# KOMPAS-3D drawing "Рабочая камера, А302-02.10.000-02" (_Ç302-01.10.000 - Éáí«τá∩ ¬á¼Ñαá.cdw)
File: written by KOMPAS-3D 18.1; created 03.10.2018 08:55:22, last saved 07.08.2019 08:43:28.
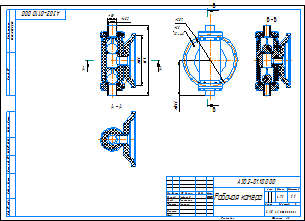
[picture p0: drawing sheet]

Sheet 1: A3, landscape

Document properties: Автор: Милов; Полное имя файла: D:\Мембранные насосы\Мембранный электропривод\А302-00.00.000 - ASTRA-302 (МЭ200)\3Д ПВХ\А302-01.10.000 - Рабочая камера.cdw; Масса: 4.93

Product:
- Part/product: Рабочая камера  | designation А302-02.10.000-02  | pos. 0
    Масса: 6.96767
    Раздел спецификации: Сборочные единицы
    Форматы листов документа: A3
  - Component [assembly]: Крышка рабочей камеры  | designation А302-02.11.000-02  | pos. 1  | Масса: 5.30764; Раздел спецификации: Сборочные единицы; Форматы листов документа: A3; source file: А302-01.11.000 - Крышка рабочей камеры.a3d
  - Component [detail]: Седло  | designation А302-01.10.001  | qty 2  | pos. 3  | Материал: Фторопласт-4  ГОСТ 10007-80 Е (density 2200 kg/m3); Масса: 0.0789763; Раздел спецификации: Детали; Форматы листов документа: A4; source file: \\192.168.87.28\Konstructor_doc\Мембранные насосы\Мембранный электропривод\А302-00.00.000 - ASTRA-302 (МЭ200)\3Д ПВХ\А302-01.10.001 - Седло.cdw, А302-01.10.001 - Седло.m3d
  - Component [assembly]: Прижим  | designation А302-01.30.000  | qty 2  | pos. 2  | Материал: Полиамид П-12Б-20  ТУ 6-05-898-73 (density 1020 kg/m3); Масса: 0.266873; Раздел спецификации: Сборочные единицы; Форматы листов документа: A3; source file: А302-01.30.000 - Прижим.a3d, А302-01.30.000 - Прижим.cdw
  - Component [detail]: Штифт 10х40  | qty 4  | pos. 86  | Масса: 0.0246804; Раздел спецификации: Детали; source file: Штифт 10х40.m3d
- Part/product: Рабочая камера  | designation А302-02.10.000-01  | pos. 0
    Масса: 10.6499
    Раздел спецификации: Сборочные единицы
    Форматы листов документа: A3
  - Component [assembly]: Крышка рабочей камеры  | designation А302-02.11.000-01  | pos. 1  | Масса: 9.08855; Раздел спецификации: Сборочные единицы; Форматы листов документа: A3; source file: А302-01.11.000 - Крышка рабочей камеры.a3d
  - Component [detail]: Седло  | designation А302-01.10.001  | qty 2  | pos. 3  | Материал: Фторопласт-4  ГОСТ 10007-80 Е (density 2200 kg/m3); Масса: 0.0789763; Раздел спецификации: Детали; Форматы листов документа: A4; source file: \\192.168.87.28\Konstructor_doc\Мембранные насосы\Мембранный электропривод\А302-00.00.000 - ASTRA-302 (МЭ200)\3Д ПВХ\А302-01.10.001 - Седло.cdw, А302-01.10.001 - Седло.m3d
  - Component [assembly]: Прижим  | designation А302-01.30.000  | qty 2  | pos. 2  | Материал: Полиамид П-12Б-20  ТУ 6-05-898-73 (density 1020 kg/m3); Масса: 0.266873; Раздел спецификации: Сборочные единицы; Форматы листов документа: A3; source file: А302-01.30.000 - Прижим.a3d
- Part/product: Рабочая камера  | designation А302-02.10.000  | pos. 0
    Масса: 6.44594
    Раздел спецификации: Сборочные единицы
    Форматы листов документа: A3
    Комментарий: Версия 2, стаканы внутри корпуса.
  - Component [assembly]: Крышка рабочей камеры  | designation А302-02.11.000  | pos. 1  | Масса: 4.87978; Раздел спецификации: Сборочные единицы; Форматы листов документа: A3; source file: А302-01.11.000 - Крышка рабочей камеры.a3d
  - Component [detail]: Седло  | designation А302-01.10.001  | qty 2  | pos. 3  | Материал: Фторопласт-4  ГОСТ 10007-80 Е (density 2200 kg/m3); Масса: 0.0789763; Раздел спецификации: Детали; Форматы листов документа: A4; source file: \\192.168.87.28\Konstructor_doc\Мембранные насосы\Мембранный электропривод\А302-00.00.000 - ASTRA-302 (МЭ200)\3Д ПВХ\А302-01.10.001 - Седло.cdw, А302-01.10.001 - Седло.m3d
  - Component [assembly]: Прижим  | designation А302-01.30.000  | qty 2  | pos. 2  | Материал: Полиамид П-12Б-20  ТУ 6-05-898-73 (density 1020 kg/m3); Масса: 0.266873; Раздел спецификации: Сборочные единицы; Форматы листов документа: A3; source file: А302-01.30.000 - Прижим.a3d
- Part/product: Рабочая камера  | designation А302-01.10.000  | pos. 0
    Масса: 5.74882
    Раздел спецификации: Сборочные единицы
    Форматы листов документа: A3
    source file: А302-01.10.000 - Рабочая камера.cdw
  - Component [detail]: Гайка шестигранная самостопорящаяся с фланцем / DIN 6927-M6 - A2-70  | qty 6  | pos. 5  | Масса: 0.00415355; Раздел спецификации: Стандартные изделия; Примечание: Нерж., / насечки; source file: ..\..\..\..\2 Стандартные изделия 3D\Гайки\DIN 6927\Гайка шестигранная самостопорящаяся с фланцем DIN 6927-M6 - A2-70.m3d
  - Component [detail]: Гайка шестигранная самостопорящаяся с фланцем / DIN 6927-M6 - A2-70  | qty 6  | pos. 5  | Масса: 0.00415355; Раздел спецификации: Стандартные изделия; source file: ..\..\..\..\2 Стандартные изделия 3D\Гайки\DIN 6927\Гайка шестигранная самостопорящаяся с фланцем DIN 6927-M6 - A2-70.m3d
  - Component [detail]: Кольцо 072-078-25 / материал EPDM ГОСТ 9833-76  | qty 2  | pos. 9  | Материал: Смесь резиновая 3063  ТУ 38-1051082-86 (density 1280 kg/m3); Масса: 0.00150018; Раздел спецификации: Прочие изделия; source file: \\192.168.87.28\Konstructor_doc\1 ПКИ 3D\РТИ\Кольца ГОСТ 9833-76\Кольцо 072-78-25 EPDM ГОСТ 9833-76.m3d
  - Component [detail]: Кольцо 072-078-25 / материал EPDM ГОСТ 9833-76  | qty 2  | pos. 9  | Материал: Смесь резиновая 3063  ТУ 38-1051082-86 (density 1280 kg/m3); Масса: 0.00150018; Раздел спецификации: Прочие изделия; source file: ..\..\..\..\1 ПКИ 3D\РТИ\Кольца ГОСТ 9833-76\Кольцо 072-78-25 EPDM ГОСТ 9833-76.m3d
  - Component [standard]: Шайба C.6.21 ГОСТ 11371-78  | qty 6  | pos. 8
      Материал: Сталь 12Х18Н10Т ГОСТ 5632-72 (density 1000 kg/m3)
      Масса: 0.00099
      Раздел спецификации: Стандартные изделия
      Примечание: Нерж.
      additional columns: Сталь 12Х18Н10Т ГОСТ 5632-72
      source file: C:\Program Files\ASCON\KOMPAS-3D V16\Libs\PartLib\DATA\vault\Methods\Kompas\3D\PLib_Washer_1_712.m3d
  - Component [standard]: Шайба 6 30Х13 ГОСТ 6402-70  | qty 6  | pos. 7
      Материал: Сталь 30Х13 ГОСТ 5632-72 (density 1000 kg/m3)
      Масса: 0.000376
      Раздел спецификации: Стандартные изделия
      Примечание: Нерж.
      additional columns: Сталь 30Х13 ГОСТ 5632-72
      source file: C:\Program Files\ASCON\KOMPAS-3D V16\Libs\PartLib\DATA\VAULT\Methods\kompas\3d\PLib_Washer_2_712.m3d
  - Component [standard]: Винт с цилиндрической головкой и шестигранным углублением под ключ ГОСТ Р ИСО  4762-М6 x 40-A2-70  | qty 6  | pos. 6  | Материал: Нержавеющая сталь (density 1000 kg/m3); Масса: 0.011; Раздел спецификации: Стандартные изделия; additional columns: ГОСТ Р ИСО 4762-2012; М6 x 40 - A2-70; Нержавеющая сталь; source file: C:\Program Files\ASCON\KOMPAS-3D V16\Libs\PartLib\DATA\vault\Methods\Kompas\3D\PLib_Screw_DIN_7984_1500.m3d
  - Component [standard]: Винт с цилиндрической головкой и / шестигранным углублением под ключ / ГОСТ Р ИСО  4762-М6 x 40-A2-70  | qty 6  | pos. 6
      Материал: Нержавеющая сталь (density 1000 kg/m3)
      Масса: 0.011
      Раздел спецификации: Стандартные изделия
      Примечание: Нерж.
      additional columns: Винт с цилиндрической головкой и шестигранным углублением под ключ; ГОСТ Р ИСО 4762-2012; М6 x 40 - A2-70; Нержавеющая сталь
      source file: C:\Program Files\ASCON\KOMPAS-3D V16\Libs\PartLib\DATA\vault\Methods\Kompas\3D\PLib_Screw_DIN_7984_1500.m3d
  - Component [standard]: Шайба 6 30Х13 ГОСТ 6402-70  | qty 6  | pos. 7  | Материал: Сталь 30Х13 ГОСТ 5632-72 (density 1000 kg/m3); Масса: 0.000376; Раздел спецификации: Стандартные изделия; additional columns: Сталь 30Х13 ГОСТ 5632-72; source file: C:\Program Files\ASCON\KOMPAS-3D V16\Libs\PartLib\DATA\VAULT\Methods\kompas\3d\PLib_Washer_2_712.m3d
  - Component [standard]: Шайба C.6.21 ГОСТ 11371-78  | qty 6  | pos. 8  | Материал: Сталь 12Х18Н10Т ГОСТ 5632-72 (density 1000 kg/m3); Масса: 0.00099; Раздел спецификации: Стандартные изделия; additional columns: Сталь 12Х18Н10Т ГОСТ 5632-72; source file: C:\Program Files\ASCON\KOMPAS-3D V16\Libs\PartLib\DATA\vault\Methods\Kompas\3D\PLib_Washer_1_712.m3d
  - Component [assembly]: Прижим  | designation А302-01.30.000  | qty 2  | pos. 2  | Материал: Полиамид П-12Б-20  ТУ 6-05-898-73 (density 1020 kg/m3); Масса: 0.266873; Раздел спецификации: Сборочные единицы; Форматы листов документа: A3; source file: \\192.168.87.28\Konstructor_doc\Мембранные насосы\Мембранный электропривод\А302-00.00.000 - ASTRA-302 (МЭ200)\3Д ПВХ\А302-01.30.000 - Прижим.cdw, А302-01.30.000 - Прижим.a3d, А302-01.30.000 - Прижим.cdw
  - Component [detail]: Стакан  | designation А302-01.10.002 3Д  | qty 2  | pos. 4  | Масса: 0.0838758; Раздел спецификации: Детали; Форматы листов документа: -; Примечание: Матрица / АСТРА302-001М; source file: А302-01.10.002 3Д - Стакан.m3d
  - Component [detail]: Седло  | designation А302-01.10.001  | qty 2  | pos. 3  | Материал: Фторопласт-4  ГОСТ 10007-80 Е (density 2200 kg/m3); Масса: 0.0789763; Раздел спецификации: Детали; Форматы листов документа: A4; source file: \\192.168.87.28\Konstructor_doc\Мембранные насосы\Мембранный электропривод\А302-00.00.000 - ASTRA-302 (МЭ200)\3Д ПВХ\А302-01.10.001 - Седло.cdw, А302-01.10.001 - Седло.m3d
  - Component [detail]: Шар @2~60mm PTFE / для мембранного насоса  | qty 2  | pos. 10  | Материал: Фторопласт-4  ГОСТ 10007-80 Е (density 2200 kg/m3); Масса: 0.248814; Раздел спецификации: Прочие изделия; Примечание: Китай; source file: ..\..\..\..\1 ПКИ 3D\2 Китай\Шар PTFE ф60.m3d
  - Component [assembly]: Крышка рабочей камеры  | designation А302-01.11.000  | pos. 1  | Масса: 4.18751; Раздел спецификации: Сборочные единицы; Форматы листов документа: A3; source file: \\192.168.87.28\Konstructor_doc\Мембранные насосы\Мембранный электропривод\А302-00.00.000 - ASTRA-302 (МЭ200)\3Д ПВХ\А302-01.11.000 - Крышка рабочей камеры.cdw, А302-01.11.000 - Крышка рабочей камеры.a3d, А302-01.11.000 - Крышка рабочей камеры.cdw

Title block, sheet 1: Наименование: Рабочая камера; designation: А302-01.10.000; Масса: 4,93; scale: 1:1; Количество листов документа: 1; organisation: ЗАО «Астерион»; Форматы листов документа: A3; stored path: \\192.168.87.28\Konstructor_doc\Мембранные насосы\Мембранный электропривод\А302-00.00.000 - ASTRA-302 (МЭ200)\3Д ПВХ\А302-01.10.000 - Рабочая камера.cdw; Разработал: Лифлянд; Проверил: Борисенко; Т. контр.: Лучихин; Разработал, date: 07.08.2019

Views: Вид 1, Местный разрез 1, Вид:2, Проекционный вид 2, Разрез Б-Б, Разрез А-А, Вид:1
Referenced files in D:\Мембранные насосы\Мембранный электропривод\А302-00.00.000 - ASTRA-302 (МЭ200)\3Д ПВХ\: А302-01.10.001 - Седло.m3d, А302-01.30.001 - Прижим.m3d, А302-01.10.002 3Д - Стакан.m3d, А302-01.31.000 - Корпус со встроенными стаканами.m3d, А302-01.12.001 - Крышка.m3d, Штифт 10х40.m3d, А302-01.30.000 - Прижим.a3d, А302-01.30.000 - Прижим.cdw, А302-01.11.000 - Крышка рабочей камеры.a3d, А302-01.12.000 - Крышка.a3d, А302-01.31.001 - Корпус.m3d, А302-01.10.000 - Рабочая камера.a3d
Referenced files in D:\Мембранные насосы\Мембранный электропривод\А302-00.00.000 - ASTRA-302 (МЭ200)\3Д ПВХ\Отработка\: Труба ПВХ PN10 50х2,4.m3d
Referenced files in D:\1 ПКИ 3D\РТИ\Кольца ГОСТ 9833-76\: Кольцо 072-78-25 EPDM ГОСТ 9833-76.m3d
Referenced files in \\192.168.87.28\Konstructor_doc\1 ПКИ 3D\РТИ\Кольца ГОСТ 9833-76\: Кольцо 072-78-25 EPDM ГОСТ 9833-76.m3d
Referenced files in D:\1 ПКИ 3D\ПВХ фитинги, трубы\: Труба PVC-U 63 4,7.m3d
Referenced files in Z:\Мембранные насосы\Мембранный электропривод\А302-00.00.000 - ASTRA-302 (МЭ200)\3Д ПВХ\: А302-01.10.000 - Рабочая камера.a3d
Referenced files in D:\1 ПКИ 3D\2 Китай\: Шар PTFE ф60.m3d
Referenced files in \\192.168.87.28\Konstructor_doc\Мембранные насосы\Мембранный электропривод\А302-00.00.000 - ASTRA-302 (МЭ200)\3Д ПВХ\: А302-01.10.001 - Седло.cdw
Referenced files: Заготовка стакан.m3d
Referenced files in C:\Program Files\ASCON\KOMPAS-3D V16\Libs\PartLib\DATA\vault\Methods\Kompas\3D\: PLib_Washer_1_712.m3d, PLib_Screw_DIN_7984_1500.m3d
Referenced files in C:\Program Files\ASCON\KOMPAS-3D V16\Libs\PartLib\DATA\VAULT\Methods\kompas\3d\: PLib_Washer_2_712.m3d
Referenced files in D:\2 Стандартные изделия 3D\Гайки\DIN 6927\: Гайка шестигранная самостопорящаяся с фланцем DIN 6927-M6 - A2-70.m3d
Referenced files in Z:\1 ПКИ 3D\2 Китай\: Шар PTFE ф60.m3d
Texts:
  Прижим
  Винт с цилиндрической головкой и
  шестигранным углублением под ключ
  ГОСТ Р ИСО  4762-М6 x 40-A2-70
  Винт
  цилиндрической
  головкой
  шестигранным
  углублением
  под
  ключ
  ГОСТ
  ИСО
  Нерж.
  Кольцо 072-078-25
  материал EPDM ГОСТ 9833-76
  Кольцо 072-078-25 / материал EPDM ГОСТ 9833-76
  Шайба 6 30Х13 ГОСТ 6402-70
  Шайба
  Штифт 10х40
  Гайка шестигранная самостопорящаяся с фланцем
  DIN 6927-M6 - A2-70
  Гайка
  шестигранная
  самостопорящаяся
  фланцем
  DIN
  Стакан
  Матрица
  АСТРА302-001М
  Матрица / АСТРА302-001М
  Шайба C.6.21 ГОСТ 11371-78
  Винт с цилиндрической головкой и шестигранным углублением под ключ ГОСТ Р ИСО  4762-М6 x 40-A2-70
  Нерж.,
  насечки
  Нерж., / насечки
  Седло
  Шар  60mm PTFE
  для мембранного насоса
  Шар @2~60mm PTFE / для мембранного насоса
  Китай
  Крышка рабочей камеры
  Крышка
  Труба ПВХ PN10 50х2,4
  Корпус
  Отвод ПВХ 90@1~ @2~50 арт.GIV050
  Отвод ПВХ 45@1~ @2~50 арт.HIV050
  Корпус со встроенными стаканами
  Труба PVC-U 50*3,7
  Гайка шестигранная самостопорящаяся с фланцем / DIN 6927-M6 - A2-70
  Винт с цилиндрической головкой и / шестигранным углублением под ключ / ГОСТ Р ИСО  4762-М6 x 40-A2-70
Dimensions and other numbers on the sheet: 387; 280; 45,2; 50; 193,5; 6,5; 12 отв.; 287; 4; 1; 58; 30Х13; 019; 21; 40Х; 1:1; 4,93; 07.08.2019; 02; 01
